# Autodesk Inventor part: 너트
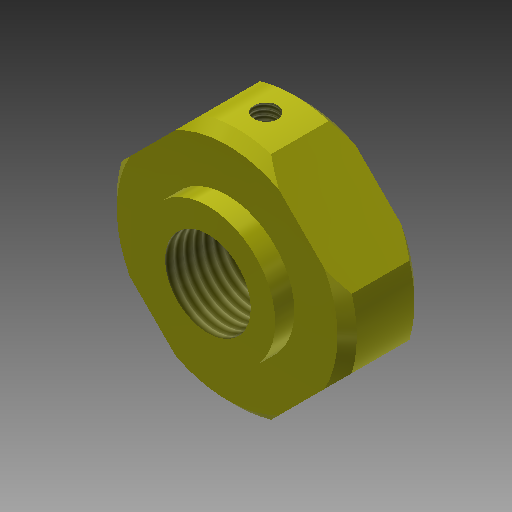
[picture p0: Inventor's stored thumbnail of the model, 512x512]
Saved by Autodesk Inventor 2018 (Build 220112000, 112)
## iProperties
Created: 2020-03
Part Number: 너트
Material: 스테인리스강
Document SubType Name: Modeling
Designer: mduedu
Density: 8.08 g/cm^3
Appearance: 노란색
Mass: 25.4811 g
Surface Area: 17.4704 cm^2
Volume: 3.1536 cm^3
Author: mduedu
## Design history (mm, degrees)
sketch "스케치1"
  geometry: C1 r 12.5 at (0, 0); 1 further point
  constraints: 1 centre point, 1 coincident
  dimensions: "d0" = 25 diameter of C1
extrude "돌출1" new body sketch "스케치1" distance "d1" = 8; taper "d2" = 0 deg
chamfer "모따기1" distance "d3" = 1; stored, may be unused: second distance "d4" = 2, angle "d5" = 45 deg
sketch "스케치2"
  geometry: L1 (-15.556, 0)-(0, 15.556); L2 (0, 15.556)-(15.556, 0); L3 (15.556, 0)-(0, -15.556); L4 (0, -15.556)-(-15.556, 0); L5 (-15.556, 0)-(15.556, 0); L6 (0, 15.556)-(0, -15.556); C1 r 12.5 at (0, 0) reference; 1 further point
  constraints: 12 end point, 2 midpoint, 2 parallel, 1 horizontal, 1 perpendicular, 1 vertical
  dimensions: "d8" = 22 distance of L1.end L2.end
extrude "돌출2" sketch "스케치2" stored distance "d10" = 8; taper "d11" = 0 deg
sketch "스케치3"
  geometry: C1 r 7 at (0, 0); 1 further point
  constraints: 1 centre point, 1 coincident
  dimensions: "d12" = 14 diameter of C1
extrude "돌출3" join sketch "스케치3" distance "d13" = 2; taper "d14" = 0 deg
hole "구멍1" diameter "d17" = 8.917; stored, may be unused: countersink angle "d21" = 90 deg, drill point angle "d23" = 118 deg; dims "d15" = 10, "d16" = 10, "d18" = 6, "d19" = 4, "d20" = 2, "d22" = 8
sketch "스케치4"
  geometry: 2 further points
  constraints: 1 vertical alignment
  dimensions: "d24" = 4 distance of point (0, 4) point (0, 0)
hole "구멍2" sketch "스케치4" at (0, 4) diameter "d25" = 2.459; stored, may be unused: countersink angle "d29" = 90 deg, drill point angle "d31" = 118 deg; dims "d26" = 6, "d27" = 4, "d28" = 2, "d30" = 8
node "솔리드1"
